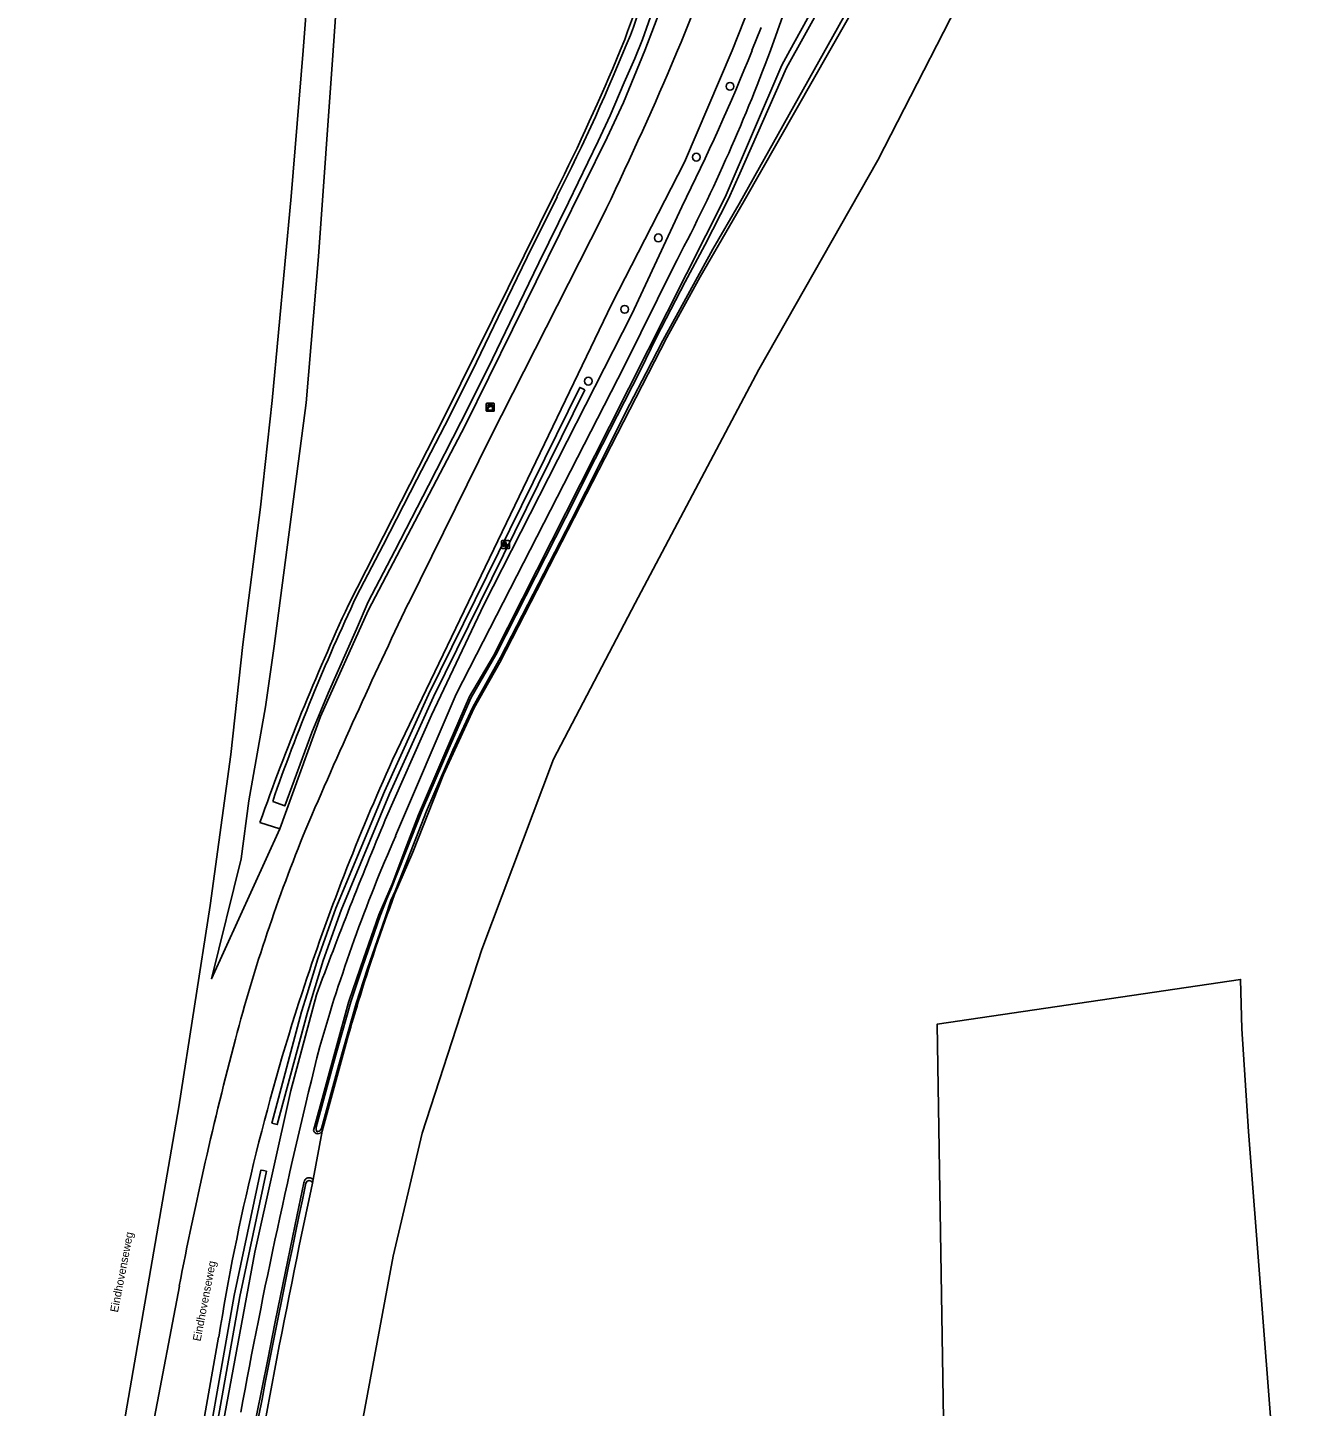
# Model space of a CAD drawing. Extents: x 162515 to 163909, y 388494 to 389773.
# Drawn here: x 162554.4 to 162715.2, y 389330.6 to 389502.9 of the extents above; entities that cross this region are included whole.
import ezdxf

# ---------------------------------------------------------------- set-up
doc = ezdxf.new("R2010")
doc.units = 0
for name, color, linetype in [('IMGEO_Berm_groen', 7, 'Continuous'), ('IMGEO_Boom', 7, 'Continuous'), ('IMGEO_Fietspad_gesloten', 7, 'Continuous'), ('IMGEO_Grasland_overig', 7, 'Continuous'), ('IMGEO_Groenvoorziening', 7, 'Continuous'), ('IMGEO_Haag', 7, 'Continuous'), ('IMGEO_Kast', 7, 'Continuous'), ('IMGEO_Lichtpunt', 7, 'Continuous'), ('IMGEO_Loofbos', 7, 'Continuous'), ('IMGEO_Openbare_ruimte_label', 7, 'Continuous'), ('IMGEO_Rijbaan_lokaal_gesloten', 7, 'Continuous'), ('IMGEO_Rijbaan_regionaal_gesloten', 7, 'Continuous'), ('IMGEO_Waterloop', 7, 'Continuous')]:
    doc.layers.add(name, color=color, linetype=linetype)

msp = doc.modelspace()

# ---------------------------------------------------------------- linework, layer by layer
at = {"layer": 'IMGEO_Berm_groen'}
for points in [[(162644.49, 389558.55), (162620.58, 389606.08), (162595.14, 389539.18), (162594.1, 389521.6), (162592.59, 389500), (162590.76, 389474.27), (162589.21, 389455.96), (162585.24, 389425.59), (162584.14, 389417.99), (162582.08, 389406.23), (162581.11, 389399), (162577.41, 389384.02), (162585.92, 389402.74)], [(162585.92, 389402.74), (162591.02, 389416.77), (162596.97, 389430.04), (162609.1, 389453.15), (162626.82, 389489.12), (162628.85, 389493.53), (162631.52, 389500), (162635.15, 389509.54), (162636.54, 389513.85)]]:
    msp.add_lwpolyline(points, dxfattribs=at)
at = {"layer": 'IMGEO_Boom'}
for centre in [(162642.17, 389495.53), (162637.96, 389486.68), (162633.22, 389476.59), (162629.01, 389467.67), (162624.48, 389458.69)]:
    msp.add_circle(centre, 0.489, dxfattribs=at)
at = {"layer": 'IMGEO_Fietspad_gesloten'}
for points in [[(162647.23, 389500), (162649.65, 389506.83), (162653.09, 389517.43)], [(162646.06, 389502.88), (162644.92, 389500)], [(162636.15, 389480.48), (162629.91, 389467.06), (162611.43, 389430.75), (162604.88, 389416.95), (162599.11, 389403.87)], [(162600.4, 389401.85), (162607.96, 389419.59), (162629.01, 389460.6), (162635.14, 389473.05)], [(162590.51, 389382), (162587.31, 389370.06), (162582.8, 389349.85), (162573.64, 389300.34), (162564.98, 389250), (162561.15, 389227.73), (162558.39, 389211.74), (162557.06, 389201.5)]]:
    msp.add_lwpolyline(points, dxfattribs=at)
for centre, radius, start, end in [((162436.17, 389578.53), 225.2, 332.0716, 339.5918), ((162401.4, 389597.72), 262.4, 333.4615, 338.135), ((163120.98, 389186.17), 565.46, 157.3561, 159.7374), ((162787.93, 389319.47), 204.82, 156.2833, 164.1145), ((163295.43, 389199.66), 726.13, 165.98283, 169.67257)]:
    msp.add_arc(centre, radius, start, end, dxfattribs=at)
at = {"layer": 'IMGEO_Grasland_overig'}
for points in [[(162673.74, 389511.91), (162660.64, 389486.29), (162645.79, 389460.14), (162630.34, 389430.94), (162620.12, 389411.44), (162611.16, 389387.65), (162603.73, 389364.73), (162600.09, 389349.34), (162595.22, 389323.12), (162589.65, 389295.27), (162587.18, 389279.33), (162585.38, 389264.9)], [(162600.27, 389394.52), (162602.54, 389399.82), (162606.39, 389409.53), (162610.2, 389417.85), (162613.42, 389423.52), (162634.26, 389464.15), (162635.68, 389466.73), (162638.44, 389471.71), (162643.96, 389481.23), (162654.64, 389500), (162658.13, 389506.14), (162669.72, 389510.24)], [(162591.21, 389364.97), (162594.48, 389376.89)], [(162590.09, 389358.94), (162591.21, 389364.97)], [(162590.09, 389358.94), (162590, 389358.45)]]:
    msp.add_lwpolyline(points, dxfattribs=at)
for centre, radius, start, end in [((162815.52, 389313.98), 229.82, 159.4843, 163.0103), ((162819.71, 389312.82), 234.16, 163.0402, 164.1223)]:
    msp.add_arc(centre, radius, start, end, dxfattribs=at)
at = {"layer": 'IMGEO_Groenvoorziening'}
for points in [[(162656.93, 389513.26), (162649.65, 389500), (162648.65, 389498.18), (162641.58, 389481.68), (162627.11, 389453.02), (162612.64, 389424.36), (162609.62, 389419.27), (162606.43, 389411.88), (162603.24, 389404.49), (162601.6, 389400.16), (162599.96, 389395.82), (162599.12, 389393.9), (162598.29, 389391.98), (162596.4, 389386.5), (162594.6, 389381.31), (162594.5, 389381.03), (162590.13, 389365.03)], [(162575.6, 389288.73), (162579.67, 389311.98), (162580.99, 389319.17), (162581.94, 389324.32), (162583, 389329.42), (162584.45, 389336.43), (162585.37, 389341.15), (162586.62, 389347.41), (162588.1, 389354.51), (162588.93, 389358.51), (162588.96, 389358.65)], [(162589.71, 389359.14), (162589.84, 389359.09), (162589.97, 389359.02), (162590.09, 389358.94)]]:
    msp.add_lwpolyline(points, dxfattribs=at)
for centre, radius, start, end in [((162590.68, 389365.23), 0.586, 199.4632, 334.0714), ((162589.67, 389358.48), 0.728, 133.081, 166.2673), ((162589.57, 389358.54), 0.611, 76.6371, 130.5315)]:
    msp.add_arc(centre, radius, start, end, dxfattribs=at)
at = {"layer": 'IMGEO_Haag'}
for points in [[(162624.03, 389457.6), (162623.72, 389457.76), (162623.4, 389457.91), (162604.51, 389419.52), (162598.99, 389407.39), (162592.92, 389392.82), (162590.68, 389386.51), (162589.35, 389382.14), (162588.66, 389379.87), (162584.94, 389365.96), (162585.28, 389365.86), (162585.62, 389365.78), (162589.34, 389379.68), (162590.05, 389382.03), (162591.35, 389386.29), (162593.58, 389392.56), (162599.63, 389407.11), (162605.14, 389419.22), (162624.03, 389457.6)], [(162580.93, 389344.3), (162576.11, 389317.16), (162574.52, 389307.03), (162574.18, 389307.09), (162573.83, 389307.14), (162575.43, 389317.28), (162580.24, 389344.43), (162583.57, 389360.1), (162583.91, 389360.03), (162584.25, 389359.95), (162580.93, 389344.3)]]:
    msp.add_lwpolyline(points, dxfattribs=at)
at = {"layer": 'IMGEO_Kast'}
for p, q in [((162611.72, 389455), (162611.72, 389455.84)), ((162611.72, 389455.84), (162611.72, 389455)), ((162611.79, 389455.93), (162612.64, 389455.93)), ((162612.64, 389455.93), (162611.79, 389455.93)), ((162612.72, 389455.85), (162612.72, 389455.01)), ((162612.72, 389455.01), (162612.72, 389455.85)), ((162612.65, 389454.93), (162611.8, 389454.93)), ((162611.8, 389454.93), (162612.65, 389454.93))]:
    msp.add_line(p, q, dxfattribs=at)
for points in [[(162611.92, 389455.72), (162612.52, 389455.72), (162612.52, 389455.63), (162611.92, 389455.63), (162611.92, 389455.72)], [(162611.92, 389455.54), (162612.52, 389455.54), (162612.52, 389455.05), (162611.92, 389455.05), (162611.92, 389455.54)]]:
    msp.add_lwpolyline(points, dxfattribs=at)
msp.add_circle((162612, 389455.39), 0.0377, dxfattribs=at)
for centre, start, end in [((162611.8, 389455.85), 92.4484, 184.2845), ((162611.8, 389455.85), 92.4484, 184.2845), ((162612.64, 389455.85), 2.4484, 94.2845), ((162612.64, 389455.85), 2.4484, 94.2845), ((162611.8, 389455), 182.4484, 274.2845), ((162611.8, 389455), 182.4484, 274.2845), ((162612.64, 389455), 272.4484, 4.2845), ((162612.64, 389455), 272.4484, 4.2845)]:
    msp.add_arc(centre, 0.0779, start, end, dxfattribs=at)
at = {"layer": 'IMGEO_Lichtpunt'}
for p, q in [((162613.63, 389438.67), (162613.63, 389437.86)), ((162613.63, 389438.67), (162613.63, 389437.86)), ((162614.53, 389438.77), (162613.72, 389438.77)), ((162614.53, 389438.77), (162613.72, 389438.77)), ((162614.62, 389437.86), (162614.62, 389438.67)), ((162614.62, 389437.86), (162614.62, 389438.67)), ((162613.72, 389437.77), (162614.53, 389437.77)), ((162613.72, 389437.77), (162614.53, 389437.77))]:
    msp.add_line(p, q, dxfattribs=at)
for points in [[(162614, 389438.33), (162614.04, 389438.31), (162613.85, 389438.04), (162613.81, 389438.07), (162614, 389438.33)], [(162614.1, 389438.29), (162614.15, 389438.29), (162614.15, 389437.96), (162614.1, 389437.96), (162614.1, 389438.29)], [(162614.21, 389438.31), (162614.25, 389438.33), (162614.44, 389438.07), (162614.4, 389438.04), (162614.21, 389438.31)]]:
    msp.add_lwpolyline(points, dxfattribs=at)
msp.add_circle((162614.13, 389438.47), 0.0994, dxfattribs=at)
for centre, start, end in [((162613.72, 389438.67), 90, 180), ((162613.72, 389438.67), 90, 180), ((162613.72, 389437.86), 180, 270), ((162613.72, 389437.86), 180, 270), ((162614.53, 389438.67), 0, 90), ((162614.53, 389438.67), 0, 90), ((162614.53, 389437.86), 270, 0), ((162614.53, 389437.86), 270, 360)]:
    msp.add_arc(centre, 0.0946, start, end, dxfattribs=at)
at = {"layer": 'IMGEO_Loofbos'}
for points in [[(162628.45, 389500), (162629.02, 389501.38)], [(162594.51, 389430.72), (162606.54, 389454.37), (162620.4, 389482.39)], [(162585.92, 389402.74), (162583.45, 389403.54)], [(162585.38, 389264.9), (162669.68, 389276.95), (162668.07, 389378.35), (162705.95, 389383.93), (162706.11, 389377.75), (162706.94, 389364.94), (162709.92, 389326.55), (162713.59, 389287.63), (162715.18, 389286.4)]]:
    msp.add_lwpolyline(points, dxfattribs=at)
for centre, radius, start, end in [((162054.39, 389709.72), 611.23, 340.07097, 343.26545), ((162376.14, 389604.6), 273.14, 333.4199, 337.4821), ((162881, 389298.3), 315.62, 155.1922, 160.522)]:
    msp.add_arc(centre, radius, start, end, dxfattribs=at)
at = {"layer": 'IMGEO_Rijbaan_lokaal_gesloten'}
for points in [[(162600.02, 389411.37), (162627.43, 389468.36), (162636.47, 389486.06), (162642.44, 389500), (162645.44, 389507.62), (162647.7, 389515.28)], [(162635.63, 389500), (162634.95, 389498.42)], [(162626.15, 389479.09), (162612.27, 389451.7), (162601.99, 389430.9)], [(162573.38, 389345.61), (162570.09, 389328.35), (162564.73, 389295.97), (162556.42, 389250), (162554.42, 389238.88)], [(162554.44, 389201.41), (162557.59, 389221.01), (162558.73, 389227.69), (162562.53, 389250), (162578.29, 389339.21)]]:
    msp.add_lwpolyline(points, dxfattribs=at)
for centre, radius, start, end in [((162457.46, 389575.29), 193.42, 337.0928, 342.4522), ((162255.56, 389659.4), 412.13, 334.056, 337.0078), ((163239.94, 389124.06), 707.91, 154.31385, 156.8215), ((162858.03, 389294.33), 283.31, 155.6008, 161.924), ((162787.74, 389321.56), 214.5, 157.7743, 165.1658), ((162858.27, 389294.25), 283.56, 161.9226, 170.8769), ((163026.24, 389258.97), 461.08, 165.2351, 169.1689)]:
    msp.add_arc(centre, radius, start, end, dxfattribs=at)
at = {"layer": 'IMGEO_Rijbaan_regionaal_gesloten'}
msp.add_lwpolyline([(162566.49, 389328.54), (162573.3, 389367.99), (162577.24, 389393.15), (162579.8, 389412.03), (162581.3, 389425.76), (162583.5, 389442.96), (162584.99, 389456.28), (162587.36, 389481.75), (162588.85, 389500), (162589.4, 389507.11), (162591.26, 389539.46), (162592.3, 389571.45), (162592.61, 389589.61), (162592.64, 389612.42)], dxfattribs=at)
at = {"layer": 'IMGEO_Waterloop'}
for points in [[(162641.85, 389533.57), (162641.01, 389530.78), (162638.84, 389523.7), (162636.65, 389516.97), (162633.95, 389509.11), (162631.24, 389501.38), (162630.27, 389499.03), (162628.95, 389496.02), (162627.2, 389491.88), (162625.71, 389488.68), (162624.4, 389486.02), (162622, 389481.02), (162618.27, 389473.47), (162615.2, 389467.11), (162611.94, 389460.37), (162608.55, 389453.55), (162604.49, 389445.66), (162600.28, 389437.47), (162596.98, 389431.12), (162595.52, 389427.71), (162591.96, 389419.68), (162589.94, 389414.8), (162586.55, 389405.61), (162585.04, 389406.17)], [(162668.74, 389510.45), (162668.64, 389510.32), (162668.52, 389510.19), (162658.39, 389506.79), (162657.56, 389506.34), (162643.33, 389480.86), (162640.01, 389475.18), (162633.79, 389463.77), (162631.71, 389459.71), (162629.67, 389455.81), (162626.03, 389448.62), (162622.32, 389441.29), (162613.52, 389424.14), (162610.05, 389417.95), (162607.54, 389412.57), (162604.25, 389404.96), (162602.24, 389399.81), (162600.33, 389394.95), (162599.78, 389393.77), (162599.09, 389391.64), (162596.85, 389385.15), (162595.48, 389380.91), (162593.29, 389373.25), (162591.12, 389365.3)], [(162590.46, 389365.32), (162590.48, 389365.46), (162592.63, 389373.44), (162594.81, 389381.12), (162596.2, 389385.36), (162598.45, 389391.88), (162599.28, 389393.98), (162599.82, 389395.16), (162601.73, 389400.01), (162603.75, 389405.17), (162607.04, 389412.78), (162609.85, 389419.17), (162612.92, 389424.47), (162621.64, 389441.63), (162625.33, 389448.98), (162628.99, 389456.16), (162631, 389460.06), (162633.01, 389464.17), (162636.58, 389471.1), (162639.04, 389475.68), (162641.98, 389481.48), (162643.39, 389484.65), (162649.25, 389497.84), (162653.92, 389506.36)], [(162595.52, 389431.81), (162598.85, 389438.21), (162603.06, 389446.39), (162607.12, 389454.28), (162610.49, 389461.08), (162613.76, 389467.81), (162616.83, 389474.17), (162620.56, 389481.73)]]:
    msp.add_lwpolyline(points, dxfattribs=at)
for centre, radius, start, end in [((162123.35, 389686.64), 539.02, 339.9616, 343.5467), ((162379.74, 389603.15), 269.7, 333.2409, 337.9596), ((162829, 389321.4), 258.27, 154.6906, 160.8385), ((162591.12, 389365.27), 0.654, 175.6637, 210.5665), ((162590.65, 389365.03), 0.138, 224.0217, 288.4721), ((162590.48, 389365.55), 0.684, 288.4475, 338.7649), ((162589.6, 389358.39), 0.405, 9.1163, 170.7405), ((164231.15, 389009.89), 1678.54, 168.01485, 170.32689), ((163673.89, 389127.31), 1108.26, 167.96191, 170.59968)]:
    msp.add_arc(centre, radius, start, end, dxfattribs=at)

# ---------------------------------------------------------------- texts
at = {"layer": 'IMGEO_Openbare_ruimte_label'}
for rotation, p in [(79.1058, (162565.7, 389342.26)), (79.0496, (162576.02, 389338.65))]:
    msp.add_text('Eindhovenseweg', height=1, rotation=rotation, dxfattribs=at).set_placement(p)

doc.saveas('drawing.dxf')
